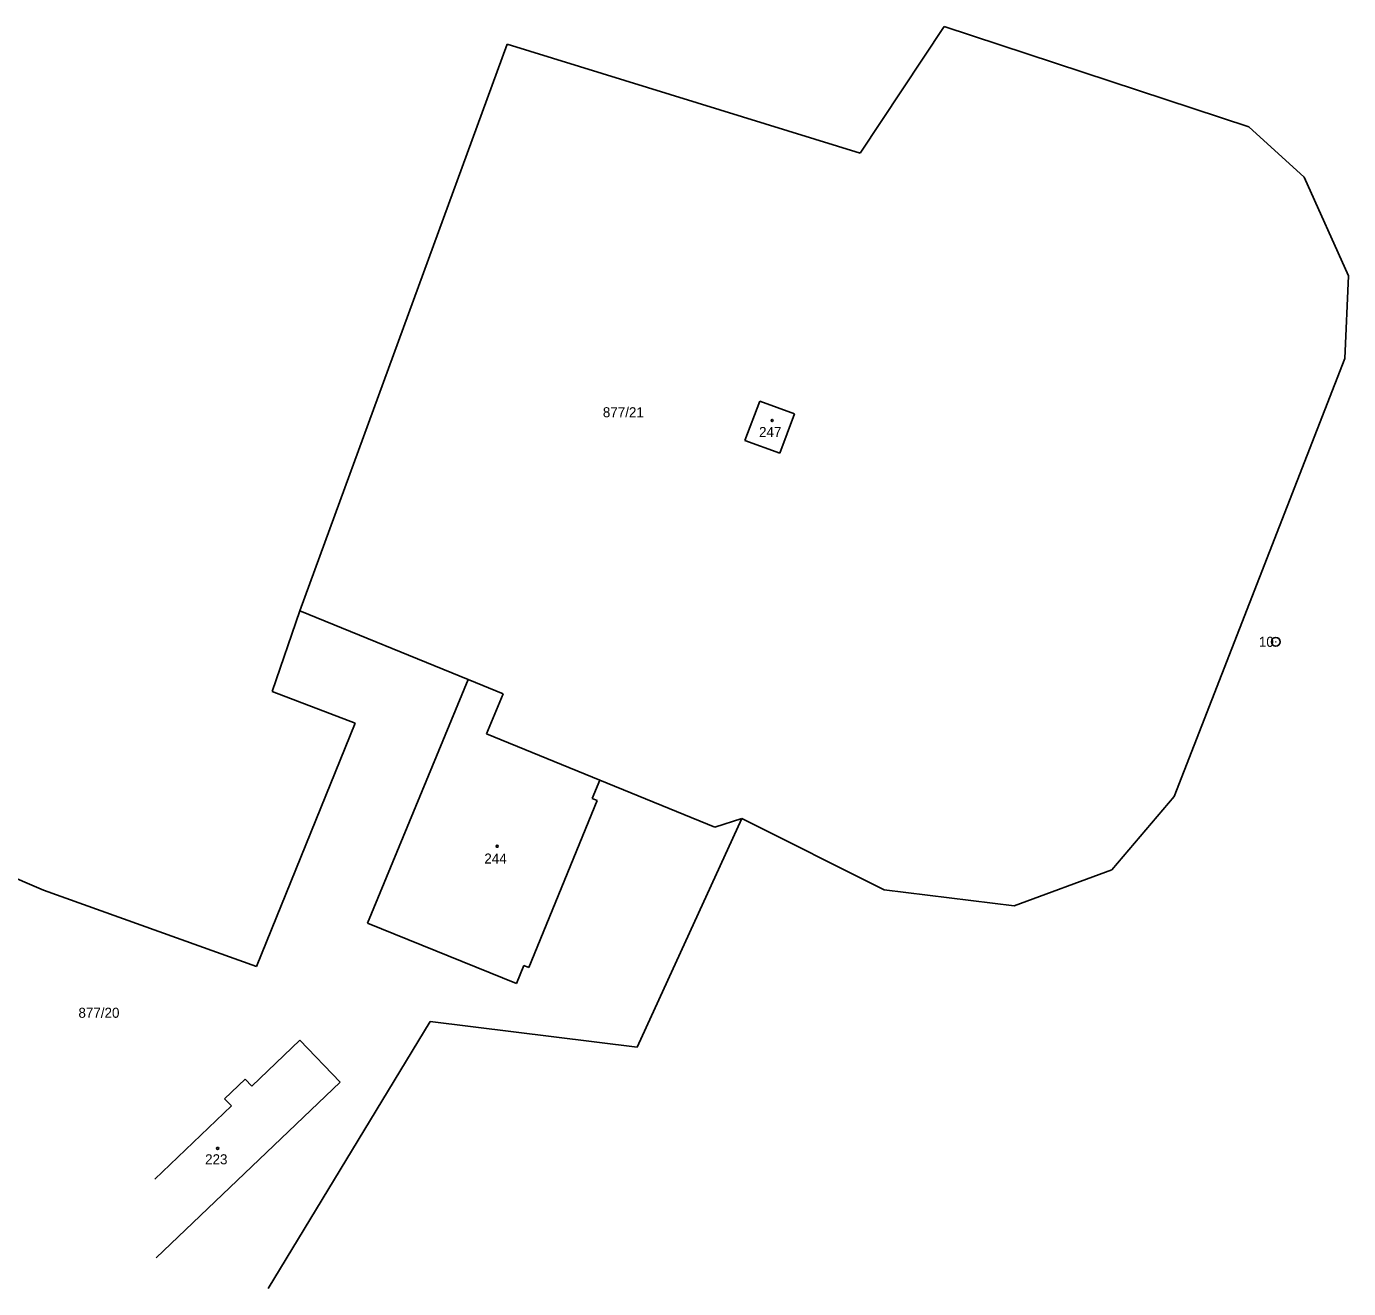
# Model space of a CAD drawing. Extents: x -749173 to -746119, y -1132678 to -1130338.
# Drawn here: x -748282.3 to -748058.1, y -1132649.2 to -1132435.1 of the extents above; entities that cross this region are included whole.
import ezdxf

# ---------------------------------------------------------------- set-up
doc = ezdxf.new("R2010")
doc.units = 0
for name, color, linetype in [('Vrstva 1', 7, 'Continuous'), ('Vrstva 17', 7, 'Continuous'), ('Vrstva 18', 7, 'Continuous'), ('Vrstva 19', 7, 'Continuous'), ('Vrstva 24', 7, 'Continuous'), ('Vrstva 25', 7, 'Continuous'), ('Vrstva 3', 7, 'Continuous'), ('Vrstva 37', 7, 'Continuous')]:
    doc.layers.add(name, color=color, linetype=linetype)

msp = doc.modelspace()

# ---------------------------------------------------------------- linework, layer by layer
at = {"layer": 'Vrstva 1'}
for points in [[(-748126.63, -1132435.12), (-748140.9, -1132456.63)], [(-748126.63, -1132435.12), (-748075, -1132452.14)], [(-748200.75, -1132438.11), (-748235.9, -1132534.27)], [(-748140.9, -1132456.63), (-748200.75, -1132438.11)], [(-748075, -1132452.14), (-748065.57, -1132460.69)], [(-748065.57, -1132460.69), (-748058.06, -1132477.41)], [(-748058.06, -1132477.41), (-748058.67, -1132491.46)], [(-748058.67, -1132491.46), (-748087.65, -1132565.77)], [(-748160.45, -1132505.37), (-748157.9, -1132498.67)], [(-748157.9, -1132498.67), (-748152.05, -1132500.83)], [(-748152.05, -1132500.83), (-748154.51, -1132507.51)], [(-748154.51, -1132507.51), (-748160.45, -1132505.37)], [(-748235.9, -1132534.27), (-748240.64, -1132547.92)], [(-748235.9, -1132534.27), (-748207.35, -1132545.9)], [(-748207.35, -1132545.9), (-748224.43, -1132587.25)], [(-748207.35, -1132545.9), (-748201.44, -1132548.35)], [(-748240.64, -1132547.92), (-748226.54, -1132553.3)], [(-748204.24, -1132555.12), (-748201.44, -1132548.35)], [(-748226.54, -1132553.3), (-748243.25, -1132594.59)], [(-748185.07, -1132563), (-748204.24, -1132555.12)], [(-748279.4, -1132581.64), (-748330.08, -1132559.88)], [(-748185.07, -1132563), (-748186.37, -1132566.09)], [(-748165.53, -1132570.96), (-748185.07, -1132563)], [(-748185.49, -1132566.45), (-748197.08, -1132594.76)], [(-748186.37, -1132566.09), (-748185.49, -1132566.45)], [(-748098.22, -1132578.21), (-748087.65, -1132565.77)], [(-748178.69, -1132608.29), (-748160.97, -1132569.48)], [(-748165.53, -1132570.96), (-748160.97, -1132569.48)], [(-748160.97, -1132569.48), (-748136.83, -1132581.57)], [(-748114.8, -1132584.32), (-748098.22, -1132578.21)], [(-748243.25, -1132594.59), (-748279.4, -1132581.64)], [(-748136.83, -1132581.57), (-748114.8, -1132584.32)], [(-748224.43, -1132587.25), (-748199.2, -1132597.48)], [(-748197.93, -1132594.41), (-748199.2, -1132597.48)], [(-748197.08, -1132594.76), (-748197.93, -1132594.41)], [(-748213.81, -1132603.95), (-748241.3, -1132649.23)], [(-748213.81, -1132603.95), (-748178.69, -1132608.29)], [(-748235.9, -1132607.11), (-748244.04, -1132614.89)], [(-748229.11, -1132614.21), (-748235.9, -1132607.11)], [(-748260.31, -1132644.02), (-748229.11, -1132614.21)], [(-748245.18, -1132613.7), (-748248.68, -1132617.04)], [(-748244.04, -1132614.89), (-748245.18, -1132613.7)], [(-748248.68, -1132617.04), (-748247.54, -1132618.24)], [(-748247.54, -1132618.24), (-748260.53, -1132630.66)]]:
    msp.add_lwpolyline(points, dxfattribs=at)
at = {"layer": 'Vrstva 24'}
msp.add_line((-748070.45, -1132539.51), (-748070.35, -1132539.51), dxfattribs=at)
msp.add_circle((-748070.4, -1132539.51), 0.756, dxfattribs=at)
at = {"layer": 'Vrstva 25'}
for centre in [(-748155.83, -1132501.97), (-748202.46, -1132574.2), (-748249.86, -1132625.45)]:
    msp.add_circle(centre, 0.175, dxfattribs=at)
at = {"layer": 'Vrstva 3'}
for points in [[(-748160.45, -1132505.37), (-748157.9, -1132498.67)], [(-748157.9, -1132498.67), (-748152.05, -1132500.83)], [(-748152.05, -1132500.83), (-748154.51, -1132507.51)], [(-748154.51, -1132507.51), (-748160.45, -1132505.37)], [(-748207.35, -1132545.9), (-748224.43, -1132587.25)], [(-748207.35, -1132545.9), (-748201.44, -1132548.35)], [(-748204.24, -1132555.12), (-748201.44, -1132548.35)], [(-748185.07, -1132563), (-748204.24, -1132555.12)], [(-748185.07, -1132563), (-748186.37, -1132566.09)], [(-748185.49, -1132566.45), (-748197.08, -1132594.76)], [(-748186.37, -1132566.09), (-748185.49, -1132566.45)], [(-748224.43, -1132587.25), (-748199.2, -1132597.48)], [(-748197.93, -1132594.41), (-748199.2, -1132597.48)], [(-748197.08, -1132594.76), (-748197.93, -1132594.41)], [(-748235.9, -1132607.11), (-748244.04, -1132614.89)], [(-748229.11, -1132614.21), (-748235.9, -1132607.11)], [(-748260.31, -1132644.02), (-748229.11, -1132614.21)], [(-748245.18, -1132613.7), (-748248.68, -1132617.04)], [(-748244.04, -1132614.89), (-748245.18, -1132613.7)], [(-748248.68, -1132617.04), (-748247.54, -1132618.24)], [(-748247.54, -1132618.24), (-748260.53, -1132630.66)]]:
    msp.add_lwpolyline(points, dxfattribs=at)
at = {"layer": 'Vrstva 37'}
for centre in [(-748155.83, -1132501.97), (-748202.46, -1132574.2), (-748249.86, -1132625.45)]:
    msp.add_circle(centre, 0.175, dxfattribs=at)

# ---------------------------------------------------------------- texts
at = {"layer": 'Vrstva 17'}
msp.add_text('10', height=1.7, dxfattribs=at).set_placement((-748073.27, -1132540.36))
at = {"layer": 'Vrstva 18'}
for s, p in [('877/21', (-748184.53, -1132501.42)), ('877/20', (-748273.47, -1132603.29))]:
    msp.add_text(s, height=1.7, dxfattribs=at).set_placement(p)
at = {"layer": 'Vrstva 19'}
for s, p in [('247', (-748158.04, -1132504.77)), ('244', (-748204.63, -1132577.13)), ('223', (-748251.99, -1132628.15))]:
    msp.add_text(s, height=1.7, dxfattribs=at).set_placement(p)

doc.saveas('drawing.dxf')
